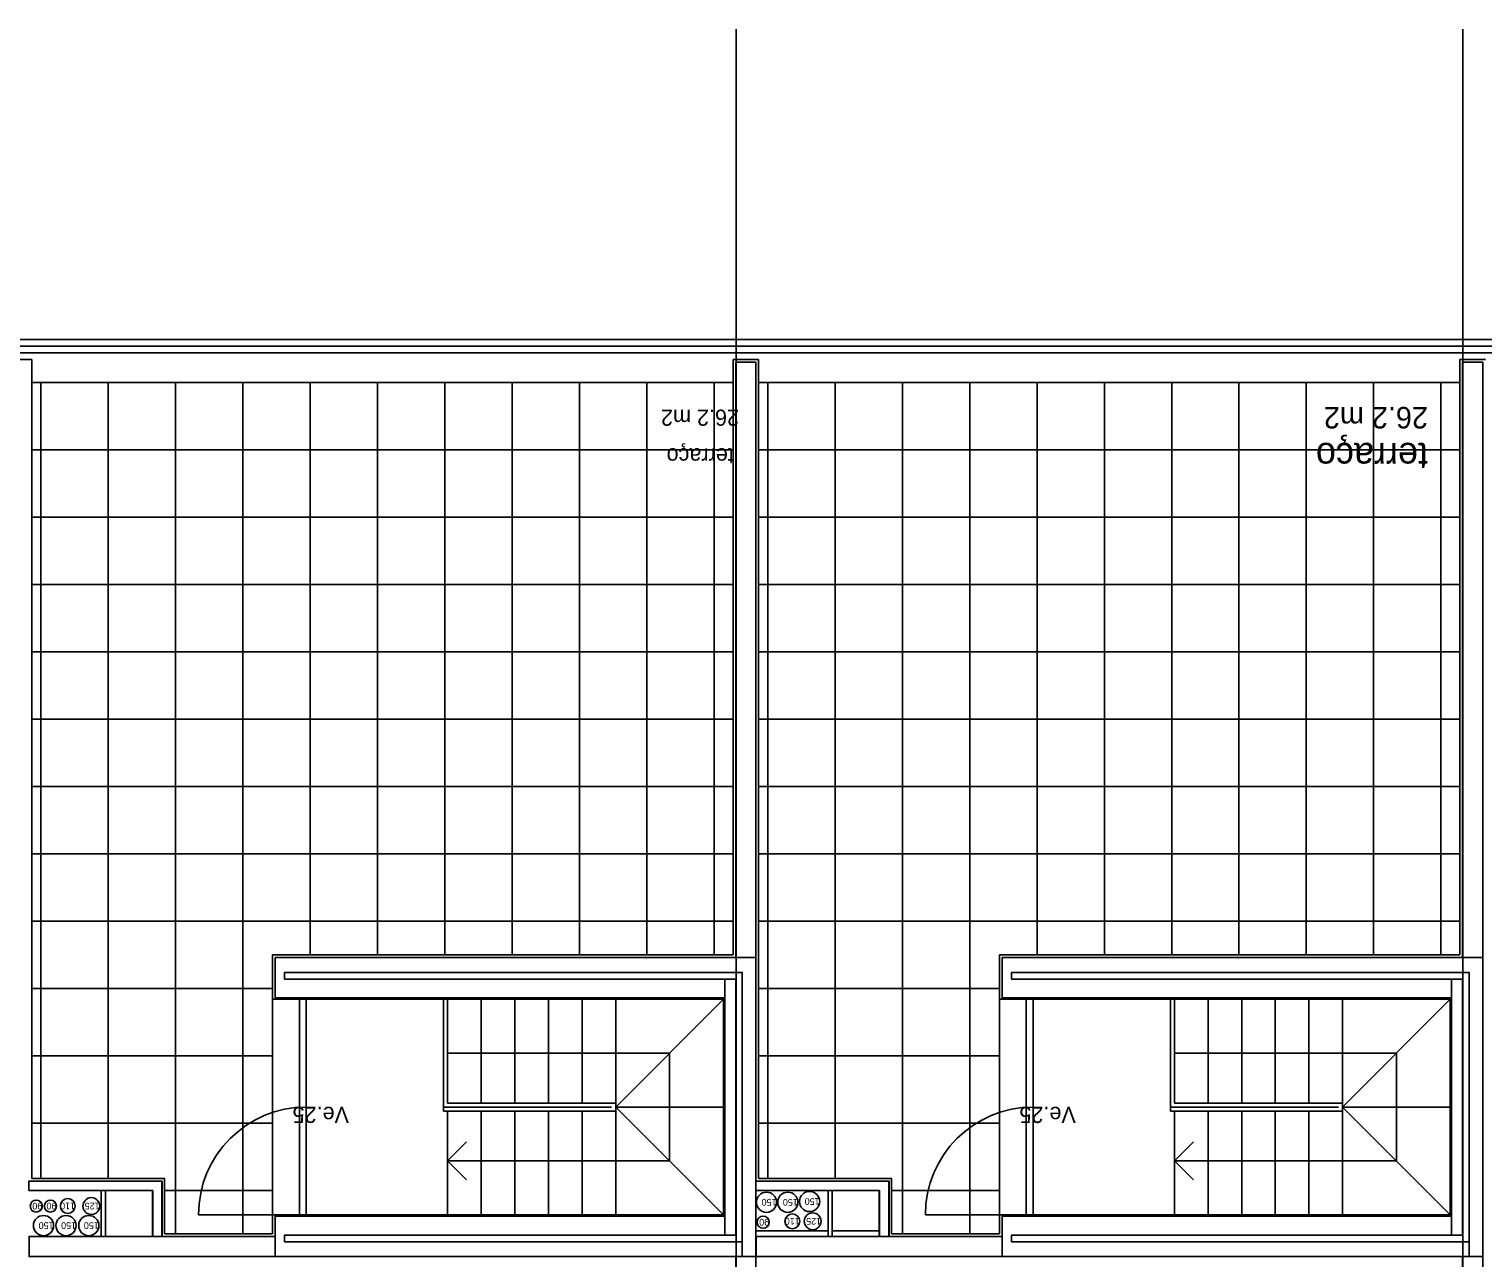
# Model space of a CAD drawing. Extents: x 1278 to 1356, y -253.7 to -224.
# Drawn here: x 1334.83 to 1345.63, y -238.74 to -229.62 of the extents above; entities that cross this region are included whole.
import ezdxf

# ---------------------------------------------------------------- set-up
doc = ezdxf.new("R2010")
doc.units = 0
for name, color, linetype in [('corte', 7, 'Continuous'), ('estereoctomias', 7, 'Continuous'), ('estrutura-eixos', 7, 'Continuous'), ('Level 1', 7, 'Continuous'), ('Level 13', 7, 'Continuous'), ('Level 2', 7, 'Continuous'), ('Level 21', 7, 'Continuous'), ('Level 40', 7, 'Continuous'), ('Level 41', 7, 'Continuous'), ('Level 60', 7, 'Continuous'), ('portas', 7, 'Continuous'), ('revestimentos', 7, 'Continuous'), ('vista', 7, 'Continuous')]:
    doc.layers.add(name, color=color, linetype=linetype)

msp = doc.modelspace()

# ---------------------------------------------------------------- linework, layer by layer
at = {"layer": 'corte'}
for p, q in [((1340.231, -232.094), (1340.081, -232.094)), ((1345.631, -232.094), (1345.481, -232.094)), ((1336.73, -236.624), (1340.13, -236.624)), ((1336.73, -236.674), (1336.73, -236.624)), ((1340.13, -236.624), (1340.13, -238.624)), ((1342.13, -236.624), (1345.53, -236.624)), ((1342.13, -236.674), (1342.13, -236.624)), ((1345.53, -236.624), (1345.53, -238.624)), ((1336.73, -236.674), (1340.081, -236.674)), ((1340.081, -236.674), (1340.081, -238.574)), ((1342.13, -236.674), (1345.481, -236.674)), ((1345.481, -236.674), (1345.481, -238.574)), ((1334.83, -238.244), (1335.75, -238.244)), ((1334.832, -238.174), (1335.82, -238.174)), ((1335.368, -238.584), (1335.368, -238.244)), ((1335.398, -238.584), (1335.398, -238.244)), ((1335.748, -238.244), (1335.748, -238.584)), ((1335.818, -238.174), (1335.818, -238.584)), ((1340.23, -238.244), (1341.15, -238.244)), ((1340.232, -238.174), (1341.22, -238.174)), ((1340.768, -238.584), (1340.768, -238.244)), ((1340.798, -238.584), (1340.798, -238.244)), ((1341.148, -238.244), (1341.148, -238.584)), ((1341.218, -238.174), (1341.218, -238.584)), ((1334.832, -238.584), (1336.66, -238.584)), ((1340.232, -238.584), (1342.06, -238.584)), ((1334.832, -238.734), (1340.231, -238.734)), ((1340.232, -238.734), (1345.631, -238.734))]:
    msp.add_line(p, q, dxfattribs=at)
at = {"layer": 'estereoctomias'}
for points in [[(1340.231, -236.514), (1340.081, -236.514), (1340.081, -232.094), (1340.231, -232.094)], [(1345.631, -236.514), (1345.481, -236.514), (1345.481, -232.094), (1345.631, -232.094)], [(1340.231, -236.514), (1340.231, -236.624), (1340.231, -238.734), (1340.13, -238.734), (1340.13, -236.624), (1336.73, -236.624), (1336.73, -236.674), (1340.081, -236.674), (1340.081, -236.814), (1340.081, -238.574), (1340, -238.574), (1340, -236.814), (1336.66, -236.814), (1336.66, -236.514)], [(1345.631, -236.514), (1345.631, -236.624), (1345.631, -238.734), (1345.53, -238.734), (1345.53, -236.624), (1342.13, -236.624), (1342.13, -236.674), (1345.481, -236.674), (1345.481, -236.814), (1345.481, -238.574), (1345.4, -238.574), (1345.4, -236.814), (1342.06, -236.814), (1342.06, -236.514)], [(1335.82, -238.584), (1335.75, -238.584), (1335.75, -238.244), (1334.83, -238.244), (1334.83, -238.174), (1335.82, -238.174)], [(1335.398, -238.584), (1335.368, -238.584), (1335.368, -238.244), (1335.398, -238.244)], [(1341.22, -238.584), (1341.15, -238.584), (1341.15, -238.244), (1340.23, -238.244), (1340.23, -238.174), (1341.22, -238.174)], [(1340.798, -238.584), (1340.768, -238.584), (1340.768, -238.244), (1340.798, -238.244)], [(1340, -238.434), (1340, -238.574), (1336.73, -238.574), (1336.73, -238.624), (1340.13, -238.624), (1340.13, -238.734), (1336.66, -238.734), (1334.832, -238.734), (1334.832, -238.584), (1336.66, -238.584), (1336.66, -238.434)], [(1345.4, -238.434), (1345.4, -238.574), (1342.13, -238.574), (1342.13, -238.624), (1345.53, -238.624), (1345.53, -238.734), (1342.06, -238.734), (1340.232, -238.734), (1340.232, -238.584), (1342.06, -238.584), (1342.06, -238.434)], [(1340.231, -240.114), (1340.081, -240.114), (1340.081, -238.734), (1340.231, -238.734)], [(1345.631, -240.114), (1345.481, -240.114), (1345.481, -238.734), (1345.631, -238.734)]]:
    msp.add_lwpolyline(points, close=True, dxfattribs=at)
at = {"layer": 'estrutura-eixos'}
for p, q in [((1340.084, -250.792), (1340.084, -229.62)), ((1345.484, -250.792), (1345.484, -229.62))]:
    msp.add_line(p, q, dxfattribs=at)
at = {"layer": 'Level 1'}
for p, q in [((1340.081, -232.094), (1340.081, -236.514)), ((1340.231, -232.094), (1340.231, -246.754)), ((1345.481, -232.094), (1345.481, -236.514)), ((1345.631, -232.094), (1345.631, -246.754)), ((1336.66, -236.514), (1340.231, -236.514)), ((1336.66, -236.514), (1336.66, -236.814)), ((1342.06, -236.514), (1345.631, -236.514)), ((1342.06, -236.514), (1342.06, -236.814)), ((1340, -236.674), (1340, -238.574)), ((1345.4, -236.674), (1345.4, -238.574)), ((1336.66, -236.814), (1340, -236.814)), ((1342.06, -236.814), (1345.4, -236.814)), ((1336.66, -238.434), (1340, -238.434)), ((1336.66, -238.434), (1336.66, -238.734)), ((1342.06, -238.434), (1345.4, -238.434)), ((1342.06, -238.434), (1342.06, -238.734)), ((1336.73, -238.574), (1340.081, -238.574)), ((1336.73, -238.574), (1336.73, -238.624)), ((1342.13, -238.574), (1345.481, -238.574)), ((1342.13, -238.574), (1342.13, -238.624)), ((1336.73, -238.624), (1340.13, -238.624)), ((1342.13, -238.624), (1345.53, -238.624)), ((1340.081, -240.114), (1340.081, -238.734)), ((1345.481, -240.114), (1345.481, -238.734))]:
    msp.add_line(p, q, dxfattribs=at)
at = {"layer": 'Level 13'}
for p, q in [((1336.84, -238.424), (1336.84, -236.824)), ((1336.89, -238.424), (1336.89, -236.824)), ((1342.24, -238.424), (1342.24, -236.824)), ((1342.29, -238.424), (1342.29, -236.824))]:
    msp.add_line(p, q, dxfattribs=at)
for centre in [(1336.89, -238.424), (1342.29, -238.424)]:
    msp.add_arc(centre, 0.8, 90, 180, dxfattribs=at)
at = {"layer": 'Level 2'}
for p, q in [((1318.543, -231.924), (1345.543, -231.924)), ((1345.543, -231.974), (1318.543, -231.974)), ((1351.318, -231.924), (1345.543, -231.924)), ((1351.268, -231.974), (1345.543, -231.974)), ((1345.543, -232.024), (1318.543, -232.024)), ((1351.219, -232.024), (1345.543, -232.024)), ((1334.852, -232.244), (1340.061, -232.244)), ((1340.252, -232.244), (1345.461, -232.244)), ((1336.64, -236.824), (1336.64, -238.424)), ((1337.91, -237.654), (1337.91, -236.824)), ((1337.94, -237.594), (1337.94, -236.824)), ((1337.94, -237.594), (1337.94, -236.824)), ((1338.19, -237.594), (1338.19, -236.824)), ((1338.44, -237.594), (1338.44, -236.824)), ((1338.69, -237.594), (1338.69, -236.824)), ((1338.94, -237.594), (1338.94, -236.824)), ((1339.19, -237.594), (1339.19, -236.824)), ((1339.19, -237.624), (1339.99, -236.824)), ((1342.04, -236.824), (1342.04, -238.424)), ((1343.31, -237.654), (1343.31, -236.824)), ((1343.34, -237.594), (1343.34, -236.824)), ((1343.34, -237.594), (1343.34, -236.824)), ((1343.59, -237.594), (1343.59, -236.824)), ((1343.84, -237.594), (1343.84, -236.824)), ((1344.09, -237.594), (1344.09, -236.824)), ((1344.34, -237.594), (1344.34, -236.824)), ((1344.59, -237.594), (1344.59, -236.824)), ((1344.59, -237.624), (1345.39, -236.824)), ((1337.94, -237.224), (1339.59, -237.224)), ((1339.59, -238.024), (1339.59, -237.224)), ((1343.34, -237.224), (1344.99, -237.224)), ((1344.99, -238.024), (1344.99, -237.224)), ((1339.19, -237.594), (1337.94, -237.594)), ((1339.19, -237.654), (1339.19, -237.594)), ((1344.59, -237.594), (1343.34, -237.594)), ((1344.59, -237.654), (1344.59, -237.594)), ((1339.159, -237.624), (1337.91, -237.624)), ((1339.19, -237.654), (1337.91, -237.654)), ((1337.94, -238.424), (1337.94, -237.654)), ((1338.19, -238.424), (1338.19, -237.654)), ((1338.44, -238.424), (1338.44, -237.654)), ((1338.69, -238.424), (1338.69, -237.654)), ((1338.94, -238.424), (1338.94, -237.654)), ((1339.99, -237.624), (1339.19, -237.624)), ((1339.19, -237.624), (1339.99, -238.424)), ((1339.19, -238.424), (1339.19, -237.654)), ((1344.559, -237.624), (1343.31, -237.624)), ((1344.59, -237.654), (1343.31, -237.654)), ((1343.34, -238.424), (1343.34, -237.654)), ((1343.59, -238.424), (1343.59, -237.654)), ((1343.84, -238.424), (1343.84, -237.654)), ((1344.09, -238.424), (1344.09, -237.654)), ((1344.34, -238.424), (1344.34, -237.654)), ((1345.39, -237.624), (1344.59, -237.624)), ((1344.59, -237.624), (1345.39, -238.424)), ((1344.59, -238.424), (1344.59, -237.654)), ((1338.082, -237.883), (1337.94, -238.024)), ((1343.482, -237.883), (1343.34, -238.024)), ((1339.59, -238.024), (1337.94, -238.024)), ((1338.082, -238.165), (1337.94, -238.024)), ((1344.99, -238.024), (1343.34, -238.024)), ((1343.482, -238.165), (1343.34, -238.024))]:
    msp.add_line(p, q, dxfattribs=at)
at = {"layer": 'Level 21'}
for p, q in [((1334.92, -238.154), (1334.92, -232.244)), ((1335.42, -238.154), (1335.42, -232.244)), ((1335.92, -238.564), (1335.92, -232.244)), ((1336.42, -238.564), (1336.42, -232.244)), ((1336.92, -236.494), (1336.92, -232.244)), ((1337.42, -236.494), (1337.42, -232.244)), ((1337.92, -236.494), (1337.92, -232.244)), ((1338.42, -236.494), (1338.42, -232.244)), ((1338.92, -236.494), (1338.92, -232.244)), ((1339.42, -236.494), (1339.42, -232.244)), ((1339.92, -236.494), (1339.92, -232.244)), ((1340.32, -238.154), (1340.32, -232.244)), ((1340.82, -238.154), (1340.82, -232.244)), ((1341.32, -238.564), (1341.32, -232.244)), ((1341.82, -238.564), (1341.82, -232.244)), ((1342.32, -236.494), (1342.32, -232.244)), ((1342.82, -236.494), (1342.82, -232.244)), ((1343.32, -236.494), (1343.32, -232.244)), ((1343.82, -236.494), (1343.82, -232.244)), ((1344.32, -236.494), (1344.32, -232.244)), ((1344.82, -236.494), (1344.82, -232.244)), ((1345.32, -236.494), (1345.32, -232.244)), ((1334.852, -232.744), (1340.061, -232.744)), ((1340.252, -232.744), (1345.461, -232.744)), ((1334.852, -233.244), (1340.061, -233.244)), ((1340.252, -233.244), (1345.461, -233.244)), ((1334.852, -233.744), (1340.061, -233.744)), ((1340.252, -233.744), (1345.461, -233.744)), ((1334.852, -234.244), (1340.061, -234.244)), ((1340.252, -234.244), (1345.461, -234.244)), ((1334.852, -234.744), (1340.061, -234.744)), ((1340.252, -234.744), (1345.461, -234.744)), ((1334.852, -235.244), (1340.061, -235.244)), ((1340.252, -235.244), (1345.461, -235.244)), ((1334.852, -235.744), (1340.061, -235.744)), ((1340.252, -235.744), (1345.461, -235.744)), ((1334.852, -236.244), (1340.061, -236.244)), ((1340.252, -236.244), (1345.461, -236.244)), ((1334.852, -236.744), (1336.64, -236.744)), ((1340.252, -236.744), (1342.04, -236.744)), ((1334.852, -237.244), (1336.64, -237.244)), ((1340.252, -237.244), (1342.04, -237.244)), ((1334.852, -237.744), (1336.64, -237.744)), ((1340.252, -237.744), (1342.04, -237.744)), ((1335.838, -238.244), (1336.64, -238.244)), ((1341.238, -238.244), (1342.04, -238.244))]:
    msp.add_line(p, q, dxfattribs=at)
at = {"layer": 'Level 41'}
for centre, radius in [((1340.31, -238.331), 0.075), ((1340.468, -238.331), 0.075), ((1340.63, -238.325), 0.075), ((1334.885, -238.359), 0.045), ((1334.99, -238.359), 0.045), ((1335.119, -238.359), 0.055), ((1335.294, -238.359), 0.0625), ((1334.939, -238.504), 0.075), ((1335.106, -238.504), 0.075), ((1335.275, -238.504), 0.075), ((1340.285, -238.479), 0.045), ((1340.502, -238.472), 0.055), ((1340.653, -238.472), 0.0625)]:
    msp.add_circle(centre, radius, dxfattribs=at)
at = {"layer": 'portas'}
for p, q in [((1336.84, -238.424), (1336.09, -238.424)), ((1342.24, -238.424), (1341.49, -238.424))]:
    msp.add_line(p, q, dxfattribs=at)
at = {"layer": 'revestimentos'}
for p, q in [((1334.851, -232.074), (1334.661, -232.074)), ((1334.851, -232.074), (1334.851, -238.154)), ((1340.061, -232.074), (1340.061, -236.494)), ((1340.251, -232.074), (1340.061, -232.074)), ((1340.251, -232.074), (1340.251, -238.154)), ((1345.461, -232.074), (1345.461, -236.494)), ((1345.651, -232.074), (1345.461, -232.074)), ((1336.64, -236.494), (1336.64, -236.824)), ((1336.64, -236.494), (1340.061, -236.494)), ((1342.04, -236.494), (1342.04, -236.824)), ((1342.04, -236.494), (1345.461, -236.494)), ((1336.64, -236.824), (1339.99, -236.824)), ((1339.99, -236.824), (1339.99, -238.424)), ((1342.04, -236.824), (1345.39, -236.824)), ((1345.39, -236.824), (1345.39, -238.424)), ((1334.852, -238.154), (1335.84, -238.154)), ((1335.838, -238.154), (1335.838, -238.564)), ((1340.252, -238.154), (1341.24, -238.154)), ((1341.238, -238.154), (1341.238, -238.564)), ((1336.64, -238.424), (1336.64, -238.564)), ((1336.64, -238.424), (1339.99, -238.424)), ((1342.04, -238.424), (1342.04, -238.564)), ((1342.04, -238.424), (1345.39, -238.424)), ((1335.838, -238.564), (1336.64, -238.564)), ((1341.238, -238.564), (1342.04, -238.564))]:
    msp.add_line(p, q, dxfattribs=at)
at = {"layer": 'vista'}
for p, q in [((1340.77, -238.544), (1340.23, -238.544)), ((1341.148, -238.544), (1340.798, -238.544))]:
    msp.add_line(p, q, dxfattribs=at)

# ---------------------------------------------------------------- texts
at = {"layer": 'Level 40'}
for p in [(1337.208, -237.622), (1342.608, -237.622)]:
    msp.add_text('Ve.25', height=0.12, rotation=180, dxfattribs=at).set_placement(p)
at = {"layer": 'Level 41'}
for s, p in [('90', (1334.93, -238.334)), ('90', (1335.035, -238.334)), ('110', (1335.174, -238.334)), ('125', (1335.356, -238.334)), ('150', (1340.385, -238.306)), ('150', (1340.543, -238.306)), ('150', (1340.705, -238.3)), ('150', (1335.014, -238.479)), ('150', (1335.181, -238.479)), ('150', (1335.35, -238.479)), ('90', (1340.33, -238.454)), ('110', (1340.557, -238.447)), ('125', (1340.716, -238.447))]:
    msp.add_text(s, height=0.05, rotation=180, dxfattribs=at).set_placement(p)
at = {"layer": 'Level 60'}
for s, height, p in [('26.2 m2', 0.16, (1345.224, -232.425)), ('26.2 m2', 0.12, (1340.106, -232.445)), ('terraço', 0.2, (1345.224, -232.692)), ('terraço', 0.12, (1340.067, -232.732))]:
    msp.add_text(s, height=height, rotation=180, dxfattribs=at).set_placement(p)

doc.saveas('drawing.dxf')
